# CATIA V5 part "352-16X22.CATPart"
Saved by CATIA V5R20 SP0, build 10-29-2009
Part number: 352-16X22
Definition: NONE
Nomenclature: 352-16X22
Source: Unknown
Description: 352-16X22
Bounding box of the stored display mesh (mm): x 0 to 22, y -11 to 11, z -11 to 11
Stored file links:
  C:\Users\Utente\Desktop\IO LAVORO\3D X SITO CF\X SITO\PLASTICA\352\352-16X22.CATPart
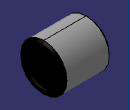
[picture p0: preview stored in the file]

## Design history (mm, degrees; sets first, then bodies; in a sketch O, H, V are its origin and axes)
Body1 "352-16X22" (main body)
  Solid1: solid without history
